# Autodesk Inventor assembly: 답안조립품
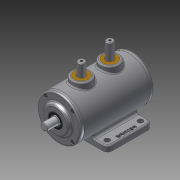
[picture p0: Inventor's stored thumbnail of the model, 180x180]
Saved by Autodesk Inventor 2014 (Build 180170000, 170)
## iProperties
Created: 2014-12
Part Number: 답안조립품
Document SubType Name: Assembly
Designer: Owner
Author: Owner
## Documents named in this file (10)
- C:\Users\Owner\Desktop\441223V1006\답안조립품.iam
- C:\Users\Owner\Desktop\441223V1006\본체.ipt
- C:\Users\Owner\Desktop\441223V1006\M4-소켓머리.ipt
- C:\Users\Owner\Desktop\441223V1006\뒷커버.ipt
- C:\Users\Owner\Desktop\441223V1006\베어링 6203.ipt
- C:\Users\Owner\Desktop\441223V1006\부시.ipt
- C:\Users\Owner\Desktop\441223V1006\슬라이더.ipt
- C:\Users\Owner\Desktop\441223V1006\앞커버.ipt
- C:\Users\Owner\Desktop\441223V1006\오일실.ipt
- C:\Users\Owner\Desktop\441223V1006\축.ipt
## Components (11 placed, 3 different names)
1. 9-M4-소켓머리:1
2. 7-베어링 6203:1
3. 8-오일실:1
4. 7-베어링 6203:2
5. 9-M4-소켓머리:2
6. 9-M4-소켓머리:3
7. 9-M4-소켓머리:4
8. 9-M4-소켓머리:5
9. 9-M4-소켓머리:6
10. 9-M4-소켓머리:7
11. 9-M4-소켓머리:8
